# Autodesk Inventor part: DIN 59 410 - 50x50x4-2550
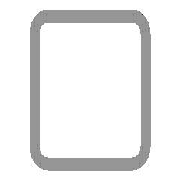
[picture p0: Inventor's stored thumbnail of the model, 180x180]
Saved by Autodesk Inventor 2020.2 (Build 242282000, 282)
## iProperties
Manager: www.cadconsulting.pl
Company: Fabian Stasiak CAD Consulting
_CCFamilyMember: 40
_CCFamilyDisplayName: DIN 59410 (Kwadrat) - Rurki stalowe o przekroju kwadratowym formowane na gorąco
_FrameMemberDoc: Frame Member File
_Version: 15.0.0
_GetPNFromCC: 1
IsCustomPart: 1
Created: 2014-02
Part Number: DIN 59 410 - 50x50x4-2550
Material: Stal, miękka
Description: Rurki stalowe o przekroju kwadratowym formowane na gorąco
Document SubType Name: Modellieren
Standard: DIN
Designer: F.Stasiak
Standards Organization: DIN
Language: pl-PL
Size Designation: 50x50x4
Categories: <MemberInstance><Categories><Category DisplayName="Kształtowniki konstrukcyjne" InternalName="089c4875-fa83-4c05-b084-43b9cc11f5ed" Mnemonic="GRDR"><CategoryPar
Stock Number: 50x50x4
Density: 7.85 g/cm^3
Appearance: Częściowo polerowana
Mass: 20313.7 g
Surface Area: 12959 cm^2
Volume: 2587.73 cm^3
Catalog Web Link: www.expertbooks.pl
G_W: 50,000 mm
G_H: 50,000 mm
G_L: 2550,000 mm
+863FC32D-3A42-4B87-B9D3-D271F46AB554+CUTDETAIL3: Wytnij
+2CF58936-3DC0-4850-BAAD-E90BCFB07CED+CUTDETAIL4: Wytnij
Author: F.Stasiak
Subject: Zbiór ćwiczeń. Autodesk Inventor 2020. Kurs Professional
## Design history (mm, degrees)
node "Płaszczyzna początkowa"
node "Płaszczyzna końcowa"
sketch "Szkic1"
  geometry: L1 (-17, 25)-(17, 25); L2 (25, 17)-(25, -17); L3 (17, -25)-(-17, -25); L4 (-25, -17)-(-25, 17); L5 (-51.32, 0)-(51.32, 0) reference; L6 (0, -51.32)-(0, 51.32) reference; L7 (-17, 21)-(17, 21); L8 (21, 17)-(21, -17); L9 (17, -21)-(-17, -21); L10 (-21, -17)-(-21, 17); A1 r 8 centre (-17, 17) between (-17, 25) and (-25, 17); A2 r 8 centre (17, 17) between (25, 17) and (17, 25); A3 r 8 centre (17, -17) between (17, -25) and (25, -17); A4 r 8 centre (-17, -17) between (-25, -17) and (-17, -25); A5 r 4 centre (-17, 17) between (-17, 21) and (-21, 17); A6 r 4 centre (17, 17) between (21, 17) and (17, 21); A7 r 4 centre (17, -17) between (17, -21) and (21, -17); A8 r 4 centre (-17, -17) between (-21, -17) and (-17, -21); 3 further points
  constraints: 16 end point, 16 point on circle, 8 centre point, 8 tangent, 6 point on line, 4 parallel, 3 equal radius, 3 perpendicular, 1 horizontal, 7 other
  dimensions: "b" = 50 distance of point (-25, 25) point (25, 25); "msp_r" = 8 radius of A1 (= 2 x ParT); "d8" = 25 distance between parallel lines of L4 L6 (= d9); "d9" = 25 distance between parallel lines of L3 L5 (= 0.5 x b); "d10" = 4 distance between parallel lines of L3 L9 (= ParT)
extrude "Bryła" new body sketch "Szkic1" taper "d4" = 0 deg; stored distance "NLG" = 10
node "Driven Length"
  sketch "Sketch2"
    geometry: L1 (0, 0)-(10, 0) reference
    constraints: 2 end point, 1 horizontal
  workplane "Work Plane3"
  sketch "Sketch3"
    geometry: L1 (-2, -25)-(12, -25) reference; L2 (-2, 2525)-(12, 2525) reference
    dimensions: "d14" = 2550 distance between parallel lines of L1 L2 (derived)
node "Płaszczyzna konstrukcyjna6"
feature "Podział3"
node "Płaszczyzna konstrukcyjna7"
feature "Podział4"
body "Solid1"
other parameters: "ParT" = 4, "G_OFFSET_START" = 25 [user parameter; used in 1 equation term], "G_OFFSET_END" = 25 [user parameter; used in 1 equation term], "d11" = -25 (= -G_OFFSET_START), "d12" = 2525 (= G_OFFSET_END + B_L), "G_L" = 2550 (= d14) [user parameter], "d13" = 90 deg
